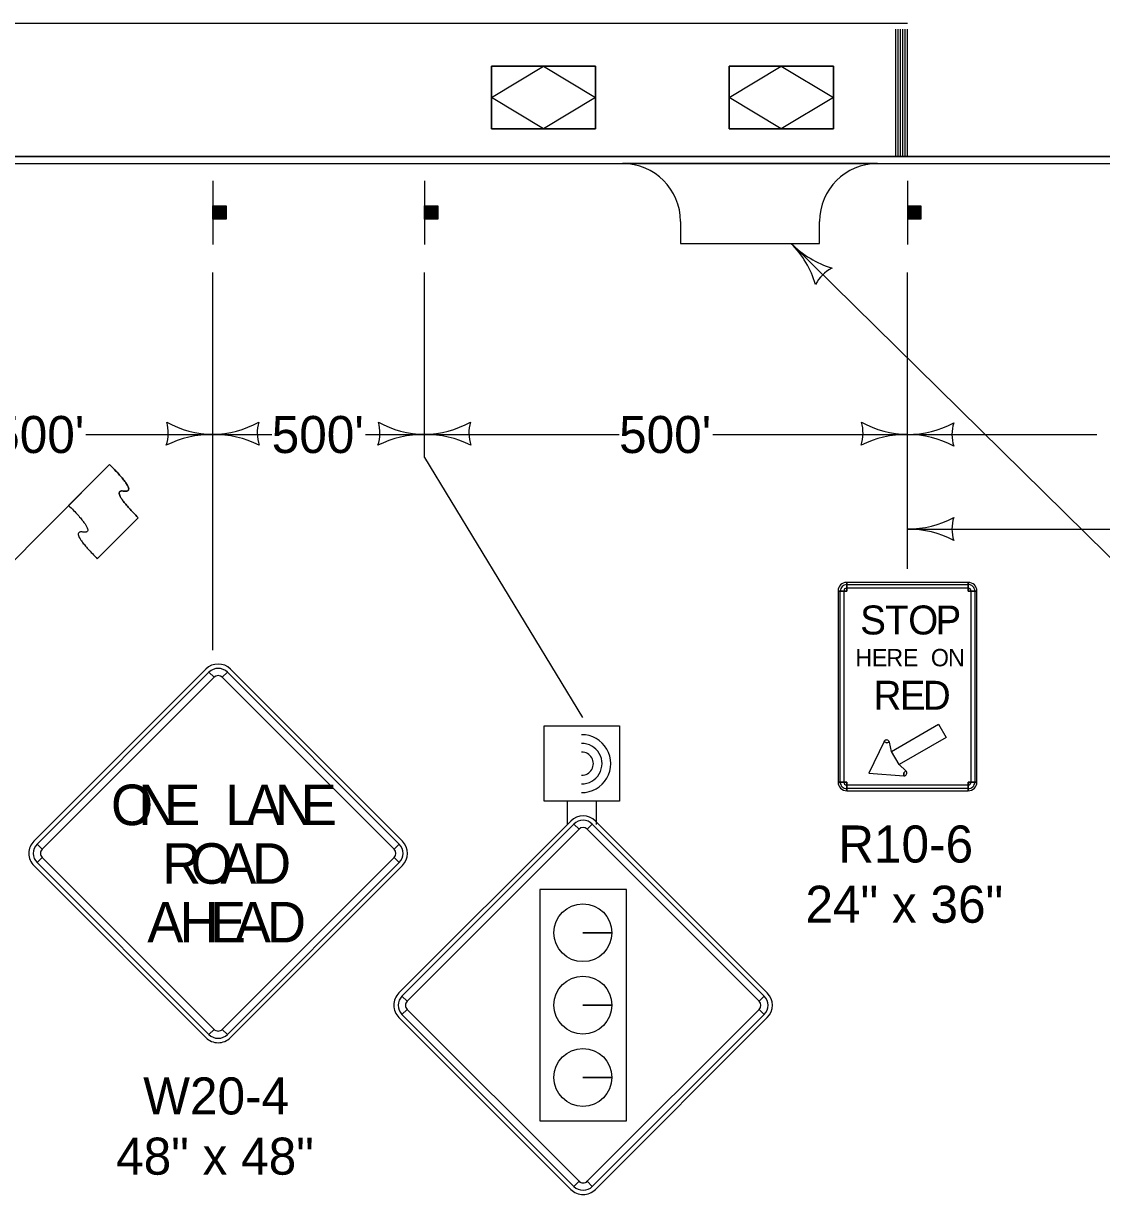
# Model space of a CAD drawing. Extents: x -2134934 to -2122394, y -2140205 to -2137036.
# Drawn here: x -2134616 to -2134151, y -2138113 to -2137608 of the extents above; entities that cross this region are included whole.
import ezdxf

# ---------------------------------------------------------------- set-up
doc = ezdxf.new("R2010")
doc.units = 0
for name, color, linetype in [('Barrier', 7, 'Continuous'), ('BridgeSuperStructureExisting', 7, 'Continuous'), ('DsnShtPlotIdentification', 7, 'Continuous'), ('DsnShtPlotShape', 7, 'Continuous'), ('dsnTextFinalPlan', 7, 'Continuous'), ('TC_Barrier', 7, 'Continuous')]:
    doc.layers.add(name, color=color, linetype=linetype)

msp = doc.modelspace()

# ---------------------------------------------------------------- linework, layer by layer
at = {"layer": 'Barrier'}
for p, q in [((-2134636.31, -2137855.42), (-2134578.99, -2137798.11)), ((-2134578.99, -2137798.11), (-2134596.67, -2137815.79)), ((-2134584.29, -2137838.78), (-2134566.61, -2137821.1)), ((-2134260.69, -2137852.75), (-2134260.69, -2137849)), ((-2134260.69, -2137851.5), (-2134260.69, -2137849.93)), ((-2134208.19, -2137849), (-2134208.19, -2137852.75)), ((-2134208.19, -2137849.93), (-2134208.19, -2137851.5)), ((-2134264.44, -2137852.75), (-2134260.69, -2137852.75)), ((-2134263.5, -2137852.75), (-2134261.94, -2137852.75)), ((-2134208.19, -2137852.75), (-2134204.44, -2137852.75)), ((-2134206.94, -2137852.75), (-2134205.38, -2137852.75)), ((-2134537.4, -2137886.48), (-2134611.65, -2137960.72)), ((-2134536.08, -2137887.8), (-2134533.87, -2137890.01)), ((-2134530.33, -2137890.01), (-2134528.12, -2137887.8)), ((-2134452.55, -2137960.72), (-2134526.8, -2137886.48)), ((-2134244.58, -2137917.73), (-2134243.48, -2137918.31)), ((-2134243.48, -2137918.31), (-2134242.26, -2137918.04)), ((-2134235.13, -2137930.38), (-2134235.98, -2137931.3)), ((-2134260.69, -2137935.24), (-2134264.44, -2137935.24)), ((-2134261.94, -2137935.24), (-2134263.5, -2137935.24)), ((-2134260.69, -2137938.99), (-2134260.69, -2137935.24)), ((-2134235.98, -2137931.3), (-2134236.03, -2137932.55)), ((-2134204.44, -2137935.24), (-2134208.19, -2137935.24)), ((-2134208.19, -2137935.24), (-2134208.19, -2137938.99)), ((-2134205.38, -2137935.24), (-2134206.94, -2137935.24)), ((-2134260.69, -2137938.06), (-2134260.69, -2137936.49)), ((-2134208.19, -2137936.49), (-2134208.19, -2137938.06)), ((-2134379.82, -2137952.07), (-2134454.06, -2138026.31)), ((-2134378.49, -2137953.39), (-2134376.28, -2137955.6)), ((-2134372.75, -2137955.6), (-2134370.54, -2137953.39)), ((-2134294.97, -2138026.31), (-2134369.21, -2137952.07)), ((-2134608.11, -2137964.26), (-2134610.32, -2137962.05)), ((-2134453.88, -2137962.05), (-2134456.08, -2137964.26)), ((-2134611.65, -2137971.33), (-2134537.4, -2138045.58)), ((-2134610.32, -2137970.01), (-2134608.11, -2137967.8)), ((-2134526.8, -2138045.58), (-2134452.55, -2137971.33)), ((-2134456.08, -2137967.8), (-2134453.88, -2137970.01)), ((-2134362.11, -2138000.29), (-2134374.61, -2138000.29)), ((-2134374.61, -2138000.29), (-2134362.11, -2138000.29)), ((-2134450.53, -2138029.85), (-2134452.74, -2138027.64)), ((-2134362.11, -2138031.54), (-2134374.61, -2138031.54)), ((-2134374.61, -2138031.54), (-2134362.11, -2138031.54)), ((-2134296.29, -2138027.64), (-2134298.5, -2138029.85)), ((-2134454.06, -2138036.92), (-2134379.82, -2138111.16)), ((-2134452.74, -2138035.59), (-2134450.53, -2138033.38)), ((-2134369.21, -2138111.16), (-2134294.97, -2138036.92)), ((-2134298.5, -2138033.38), (-2134296.29, -2138035.59)), ((-2134533.87, -2138042.04), (-2134536.08, -2138044.25)), ((-2134528.12, -2138044.25), (-2134530.33, -2138042.04)), ((-2134362.11, -2138062.79), (-2134374.61, -2138062.79)), ((-2134374.61, -2138062.79), (-2134362.11, -2138062.79)), ((-2134376.28, -2138107.63), (-2134378.49, -2138109.84)), ((-2134370.54, -2138109.84), (-2134372.75, -2138107.63))]:
    msp.add_line(p, q, dxfattribs=at)
for points in [[(-2134260.69, -2137938.99), (-2134208.19, -2137938.99), (-2134208.19, -2137935.24), (-2134204.44, -2137935.24), (-2134204.44, -2137852.75), (-2134208.19, -2137852.75), (-2134208.19, -2137849), (-2134260.69, -2137849), (-2134260.69, -2137852.75), (-2134264.44, -2137852.75), (-2134264.44, -2137935.24), (-2134260.69, -2137935.24), (-2134260.69, -2137938.99)], [(-2134208.19, -2137851.5), (-2134260.69, -2137851.5), (-2134260.69, -2137849.93), (-2134208.19, -2137849.93), (-2134208.19, -2137851.5)], [(-2134261.94, -2137852.75), (-2134261.94, -2137935.24), (-2134263.5, -2137935.24), (-2134263.5, -2137852.75), (-2134261.94, -2137852.75)], [(-2134206.94, -2137935.24), (-2134206.94, -2137852.75), (-2134205.38, -2137852.75), (-2134205.38, -2137935.24), (-2134206.94, -2137935.24)], [(-2134536.08, -2137887.8), (-2134610.32, -2137962.05), (-2134608.11, -2137964.26), (-2134533.87, -2137890.01), (-2134536.08, -2137887.8)], [(-2134453.88, -2137962.05), (-2134528.12, -2137887.8), (-2134530.33, -2137890.01), (-2134456.08, -2137964.26), (-2134453.88, -2137962.05)], [(-2134221.07, -2137910.24), (-2134217.79, -2137915.93), (-2134238.1, -2137927.65), (-2134241.38, -2137921.97), (-2134221.07, -2137910.24)], [(-2134251.09, -2137931.37), (-2134236.03, -2137932.55), (-2134235.98, -2137931.3), (-2134235.13, -2137930.38), (-2134238.1, -2137927.65), (-2134241.38, -2137921.97), (-2134242.26, -2137918.04), (-2134243.48, -2137918.31), (-2134244.58, -2137917.73), (-2134251.09, -2137931.37)], [(-2134260.69, -2137936.49), (-2134208.19, -2137936.49), (-2134208.19, -2137938.06), (-2134260.69, -2137938.06), (-2134260.69, -2137936.49)], [(-2134378.49, -2137953.39), (-2134452.74, -2138027.64), (-2134450.53, -2138029.85), (-2134376.28, -2137955.6), (-2134378.49, -2137953.39)], [(-2134296.29, -2138027.64), (-2134370.54, -2137953.39), (-2134372.75, -2137955.6), (-2134298.5, -2138029.85), (-2134296.29, -2138027.64)], [(-2134610.32, -2137970.01), (-2134536.08, -2138044.25), (-2134533.87, -2138042.04), (-2134608.11, -2137967.8), (-2134610.32, -2137970.01)], [(-2134528.12, -2138044.25), (-2134453.88, -2137970.01), (-2134456.08, -2137967.8), (-2134530.33, -2138042.04), (-2134528.12, -2138044.25)], [(-2134355.78, -2137981.67), (-2134393.25, -2137981.67), (-2134393.25, -2138081.56), (-2134355.78, -2138081.56), (-2134355.78, -2137981.67)], [(-2134452.74, -2138035.59), (-2134378.49, -2138109.84), (-2134376.28, -2138107.63), (-2134450.53, -2138033.38), (-2134452.74, -2138035.59)], [(-2134370.54, -2138109.84), (-2134296.29, -2138035.59), (-2134298.5, -2138033.38), (-2134372.75, -2138107.63), (-2134370.54, -2138109.84)]]:
    msp.add_lwpolyline(points, close=True, dxfattribs=at)
for centre in [(-2134374.61, -2138000.29), (-2134374.61, -2138031.54), (-2134374.61, -2138062.79)]:
    msp.add_circle(centre, 12.5, dxfattribs=at)
for centre, radius, start, end in [((-2134260.69, -2137852.75), 3.75, 90.0002, 179.9998), ((-2134260.69, -2137852.75), 2.81, 90.0002, 179.9998), ((-2134208.19, -2137852.75), 3.75, 0, 90.0002), ((-2134208.19, -2137852.75), 2.81, 0, 90.0002), ((-2134260.69, -2137852.75), 1.25, 90.0002, 179.9998), ((-2134208.19, -2137852.75), 1.25, 0, 90.0002), ((-2134532.1, -2137891.78), 7.5, 45, 134.9997), ((-2134532.1, -2137891.78), 5.62, 45, 134.9997), ((-2134532.1, -2137891.78), 2.5, 45, 134.9997), ((-2134243.48, -2137918.31), 1.25, 12.6223, 152.2756), ((-2134235.98, -2137931.3), 1.25, 267.7243, 47.3776), ((-2134260.69, -2137935.24), 3.75, 179.9998, 270.0001), ((-2134260.69, -2137935.24), 2.81, 179.9998, 270.0001), ((-2134260.69, -2137935.24), 1.25, 179.9998, 270.0001), ((-2134208.19, -2137935.24), 3.75, 270.0001, 0.0003), ((-2134208.19, -2137935.24), 2.81, 270.0001, 0.0003), ((-2134208.19, -2137935.24), 1.25, 270.0001, 0.0003), ((-2134374.51, -2137957.37), 7.5, 45, 134.9997), ((-2134374.51, -2137957.37), 5.62, 45, 134.9997), ((-2134374.51, -2137957.37), 2.5, 45, 134.9997), ((-2134606.34, -2137966.03), 7.5, 134.9997, 225), ((-2134457.85, -2137966.03), 7.5, 315.0002, 44.9998), ((-2134606.34, -2137966.03), 5.62, 134.9997, 225), ((-2134606.34, -2137966.03), 2.5, 134.9997, 225), ((-2134457.85, -2137966.03), 2.5, 315.0002, 44.9998), ((-2134457.85, -2137966.03), 5.62, 315.0002, 44.9998), ((-2134448.76, -2138031.62), 7.5, 134.9997, 225), ((-2134300.27, -2138031.62), 7.5, 315.0002, 44.9998), ((-2134448.76, -2138031.62), 5.62, 134.9997, 225), ((-2134448.76, -2138031.62), 2.5, 134.9997, 225), ((-2134300.27, -2138031.62), 2.5, 315.0002, 44.9998), ((-2134300.27, -2138031.62), 5.62, 315.0002, 44.9998), ((-2134532.1, -2138040.27), 2.5, 225, 315.0002), ((-2134532.1, -2138040.27), 7.5, 225, 315.0002), ((-2134532.1, -2138040.27), 5.62, 225, 315.0002), ((-2134374.51, -2138105.86), 2.5, 225, 315.0002), ((-2134374.51, -2138105.86), 7.5, 225, 315.0002), ((-2134374.51, -2138105.86), 5.62, 225, 315.0002)]:
    msp.add_arc(centre, radius, start, end, dxfattribs=at)
for points in [[(-2134566.61, -2137821.1), (-2134578.99, -2137808.72), (-2134566.61, -2137810.49), (-2134578.99, -2137798.11)], [(-2134596.67, -2137815.79), (-2134584.29, -2137828.17), (-2134596.66, -2137826.4), (-2134584.29, -2137838.78)]]:
    msp.add_open_spline(points, degree=2, dxfattribs=at)
at = {"layer": 'BridgeSuperStructureExisting'}
for p, q in [((-2134239.44, -2137665.16), (-2134239.44, -2137610.16)), ((-2134238.44, -2137665.16), (-2134238.44, -2137610.16)), ((-2134237.44, -2137665.16), (-2134237.44, -2137610.16)), ((-2134236.44, -2137665.16), (-2134236.44, -2137610.16)), ((-2134235.44, -2137665.16), (-2134235.44, -2137610.16)), ((-2134234.44, -2137665.16), (-2134234.44, -2137610.16)), ((-2134414.12, -2137653.13), (-2134414.12, -2137626.13)), ((-2134414.12, -2137626.13), (-2134369.12, -2137626.13)), ((-2134414.12, -2137653.13), (-2134414.12, -2137626.13)), ((-2134414.12, -2137626.13), (-2134369.12, -2137626.13)), ((-2134369.12, -2137626.13), (-2134414.12, -2137626.13)), ((-2134414.12, -2137626.13), (-2134414.12, -2137653.13)), ((-2134369.12, -2137653.13), (-2134369.12, -2137626.13)), ((-2134369.12, -2137626.13), (-2134369.12, -2137653.13)), ((-2134369.12, -2137653.13), (-2134369.12, -2137626.13)), ((-2134311.44, -2137653.13), (-2134311.44, -2137626.13)), ((-2134311.44, -2137626.13), (-2134266.44, -2137626.13)), ((-2134311.44, -2137653.13), (-2134311.44, -2137626.13)), ((-2134311.44, -2137626.13), (-2134266.44, -2137626.13)), ((-2134266.44, -2137626.13), (-2134311.44, -2137626.13)), ((-2134311.44, -2137626.13), (-2134311.44, -2137653.13)), ((-2134266.44, -2137653.13), (-2134266.44, -2137626.13)), ((-2134266.44, -2137626.13), (-2134266.44, -2137653.13)), ((-2134266.44, -2137653.13), (-2134266.44, -2137626.13)), ((-2134414.12, -2137653.13), (-2134369.12, -2137653.13)), ((-2134369.12, -2137653.13), (-2134414.12, -2137653.13)), ((-2134414.12, -2137653.13), (-2134369.12, -2137653.13)), ((-2134311.44, -2137653.13), (-2134266.44, -2137653.13)), ((-2134266.44, -2137653.13), (-2134311.44, -2137653.13)), ((-2134311.44, -2137653.13), (-2134266.44, -2137653.13)), ((-2134884.44, -2137665.16), (-2133384.44, -2137665.16)), ((-2134247.44, -2137668.16), (-2134357.44, -2137668.16)), ((-2134534.44, -2137675.66), (-2134534.44, -2137703.16)), ((-2134443.04, -2137675.66), (-2134443.04, -2137703.16)), ((-2134234.44, -2137675.66), (-2134234.44, -2137703.16)), ((-2134534.03, -2137692.11), (-2134534.03, -2137686.52)), ((-2134533.75, -2137686.52), (-2134533.75, -2137692.11)), ((-2134533.48, -2137692.11), (-2134533.48, -2137686.52)), ((-2134533.22, -2137686.52), (-2134533.22, -2137692.11)), ((-2134533, -2137692.11), (-2134533, -2137686.52)), ((-2134532.79, -2137686.52), (-2134532.79, -2137692.11)), ((-2134532.45, -2137692.11), (-2134532.45, -2137686.52)), ((-2134532.19, -2137686.52), (-2134532.19, -2137692.11)), ((-2134531.97, -2137692.11), (-2134531.98, -2137686.52)), ((-2134531.65, -2137686.52), (-2134531.65, -2137692.11)), ((-2134531.27, -2137692.11), (-2134531.27, -2137686.52)), ((-2134530.84, -2137686.52), (-2134530.84, -2137692.11)), ((-2134530.62, -2137692.11), (-2134530.63, -2137686.52)), ((-2134530.2, -2137686.52), (-2134530.18, -2137692.11)), ((-2134529.98, -2137692.11), (-2134529.98, -2137686.52)), ((-2134529.66, -2137686.52), (-2134529.66, -2137692.11)), ((-2134529.43, -2137692.11), (-2134529.43, -2137686.52)), ((-2134529.12, -2137686.52), (-2134529.12, -2137692.11)), ((-2134442.63, -2137692.11), (-2134442.63, -2137686.52)), ((-2134442.35, -2137686.52), (-2134442.35, -2137692.11)), ((-2134442.08, -2137692.11), (-2134442.08, -2137686.52)), ((-2134441.82, -2137686.52), (-2134441.82, -2137692.11)), ((-2134441.6, -2137692.11), (-2134441.6, -2137686.52)), ((-2134441.39, -2137686.52), (-2134441.39, -2137692.11)), ((-2134441.05, -2137692.11), (-2134441.05, -2137686.52)), ((-2134440.79, -2137686.52), (-2134440.79, -2137692.11)), ((-2134440.56, -2137692.11), (-2134440.58, -2137686.52)), ((-2134440.25, -2137686.52), (-2134440.25, -2137692.11)), ((-2134439.87, -2137692.11), (-2134439.87, -2137686.52)), ((-2134439.44, -2137686.52), (-2134439.44, -2137692.11)), ((-2134439.21, -2137692.11), (-2134439.23, -2137686.52)), ((-2134438.8, -2137686.52), (-2134438.78, -2137692.11)), ((-2134438.58, -2137692.11), (-2134438.58, -2137686.52)), ((-2134438.26, -2137686.52), (-2134438.26, -2137692.11)), ((-2134438.03, -2137692.11), (-2134438.03, -2137686.52)), ((-2134437.71, -2137686.52), (-2134437.71, -2137692.11)), ((-2134234.03, -2137692.11), (-2134234.03, -2137686.52)), ((-2134233.75, -2137686.52), (-2134233.75, -2137692.11)), ((-2134233.49, -2137692.11), (-2134233.49, -2137686.52)), ((-2134233.22, -2137686.52), (-2134233.22, -2137692.11)), ((-2134233, -2137692.11), (-2134233, -2137686.52)), ((-2134232.79, -2137686.52), (-2134232.79, -2137692.11)), ((-2134232.45, -2137692.11), (-2134232.45, -2137686.52)), ((-2134232.19, -2137686.52), (-2134232.19, -2137692.11)), ((-2134231.97, -2137692.11), (-2134231.99, -2137686.52)), ((-2134231.65, -2137686.52), (-2134231.65, -2137692.11)), ((-2134231.27, -2137692.11), (-2134231.27, -2137686.52)), ((-2134230.84, -2137686.52), (-2134230.84, -2137692.11)), ((-2134230.62, -2137692.11), (-2134230.64, -2137686.52)), ((-2134230.2, -2137686.52), (-2134230.19, -2137692.11)), ((-2134229.98, -2137692.11), (-2134229.98, -2137686.52)), ((-2134229.66, -2137686.52), (-2134229.66, -2137692.11)), ((-2134229.44, -2137692.11), (-2134229.44, -2137686.52)), ((-2134229.12, -2137686.52), (-2134229.12, -2137692.11)), ((-2134096.53, -2137887.94), (-2134284.66, -2137702.65)), ((-2134534.44, -2137878.33), (-2134534.44, -2137715.16)), ((-2134443.04, -2137795.16), (-2134443.04, -2137715.16)), ((-2134234.44, -2137843.11), (-2134234.44, -2137715.16)), ((-2134589.19, -2137785.16), (-2134534.44, -2137785.16)), ((-2134534.44, -2137785.16), (-2134508.99, -2137785.16)), ((-2134468.49, -2137785.16), (-2134443.04, -2137785.16)), ((-2134443.04, -2137785.16), (-2134358.99, -2137785.16)), ((-2134318.49, -2137785.16), (-2134234.44, -2137785.16)), ((-2134234.44, -2137785.16), (-2134152.68, -2137785.16)), ((-2134443.04, -2137795.16), (-2134374.84, -2137907.34)), ((-2134234.44, -2137825.98), (-2133930.88, -2137825.98)), ((-2134381.36, -2137943.52), (-2134381.36, -2137953.52)), ((-2134368.86, -2137943.52), (-2134368.86, -2137953.52))]:
    msp.add_line(p, q, dxfattribs=at)
for points in [[(-2134534.35, -2137692.11), (-2134534.35, -2137686.48), (-2134528.72, -2137686.48), (-2134528.72, -2137692.11)], [(-2134442.95, -2137692.11), (-2134442.95, -2137686.48), (-2134437.32, -2137686.48), (-2134437.32, -2137692.11)], [(-2134234.35, -2137692.11), (-2134234.35, -2137686.48), (-2134228.72, -2137686.48), (-2134228.72, -2137692.11)], [(-2134391.36, -2137943.52), (-2134391.36, -2137911.02), (-2134358.86, -2137911.02), (-2134358.86, -2137943.52)]]:
    msp.add_lwpolyline(points, close=True, dxfattribs=at)
msp.add_lwpolyline([(-2134332.44, -2137693.16), (-2134332.44, -2137702.65), (-2134272.44, -2137702.65), (-2134272.44, -2137693.16)], dxfattribs=at)
for centre, radius, start, end in [((-2134357.44, -2137693.16), 25, 0, 90), ((-2134247.44, -2137693.16), 25, 90, 180), ((-2134570.06, -2137784.54), 16.42, 341.2666, 16.7334), ((-2134533.69, -2137742.67), 42.5, 240.9275, 268.9824), ((-2134535.2, -2137742.67), 42.5, 271.0176, 299.0725), ((-2134498.82, -2137784.54), 16.42, 163.2666, 198.7334), ((-2134478.66, -2137784.54), 16.42, 341.2666, 16.7334), ((-2134442.29, -2137742.67), 42.5, 240.9275, 268.9824), ((-2134443.79, -2137742.67), 42.5, 271.0176, 299.0725), ((-2134407.42, -2137784.54), 16.42, 163.2666, 198.7334), ((-2134270.06, -2137784.54), 16.42, 341.2666, 16.7334), ((-2134233.69, -2137742.67), 42.5, 240.9275, 268.9824), ((-2134234.44, -2137742.66), 42.5, 270, 298.0725), ((-2134198.81, -2137785.16), 16.42, 162.2666, 197.7334), ((-2134535.17, -2137827.65), 42.5, 89.0176, 117.0725), ((-2134533.71, -2137827.65), 42.5, 62.9275, 90.9824), ((-2134443.77, -2137827.65), 42.5, 89.0176, 117.0725), ((-2134442.31, -2137827.65), 42.5, 62.9275, 90.9824), ((-2134235.17, -2137827.65), 42.5, 89.0176, 117.0725), ((-2134234.44, -2137827.66), 42.5, 61.9275, 90), ((-2134375.1, -2137927.28), 12.5, 269.4041, 90.5445), ((-2134375.1, -2137927.28), 12.5, 269.4041, 90.5445), ((-2134375.1, -2137927.28), 8.75, 269.4041, 90.5445), ((-2134375.1, -2137927.28), 5, 269.4041, 90.5445)]:
    msp.add_arc(centre, radius, start, end, dxfattribs=at)
at = {"layer": 'DsnShtPlotIdentification'}
for p, q in [((-2134234.44, -2137607.66), (-2134886.94, -2137607.66)), ((-2134884.44, -2137665.16), (-2133384.44, -2137665.16)), ((-2134884.44, -2137665.16), (-2133384.44, -2137665.16)), ((-2134239.44, -2137665.16), (-2134884.44, -2137665.16)), ((-2134884.44, -2137668.16), (-2133384.44, -2137668.16)), ((-2134884.44, -2137668.16), (-2133384.44, -2137668.16)), ((-2134238.44, -2137665.16), (-2134239.44, -2137665.16)), ((-2134237.44, -2137665.16), (-2134238.44, -2137665.16)), ((-2134236.44, -2137665.16), (-2134237.44, -2137665.16)), ((-2133384.44, -2137665.16), (-2134234.44, -2137665.16))]:
    msp.add_line(p, q, dxfattribs=at)
msp.add_lwpolyline([(-2134234.44, -2137665.16), (-2134235.44, -2137665.16), (-2134236.44, -2137665.16)], dxfattribs=at)
at = {"layer": 'DsnShtPlotShape'}
for centre, radius, start, end in [((-2134314.86, -2137732.56), 42.5, 16.6579, 44.7304), ((-2134254.47, -2137672.74), 42.5, 224.7304, 252.8028), ((-2134259.59, -2137727.96), 16.42, 116.997, 152.4637), ((-2134234.44, -2137783.48), 42.5, 270, 298.0725), ((-2134198.81, -2137825.98), 16.42, 162.2666, 197.7334), ((-2134234.44, -2137868.48), 42.5, 61.9275, 90)]:
    msp.add_arc(centre, radius, start, end, dxfattribs=at)
at = {"layer": 'dsnTextFinalPlan'}
for points in [[(-2134414.12, -2137639.63), (-2134391.62, -2137626.13), (-2134369.12, -2137639.63), (-2134391.62, -2137653.13)], [(-2134311.44, -2137639.63), (-2134288.94, -2137626.13), (-2134266.44, -2137639.63), (-2134288.94, -2137653.13)]]:
    msp.add_lwpolyline(points, close=True, dxfattribs=at)
at = {"layer": 'TC_Barrier'}
msp.add_line((-2134566.61, -2137821.1), (-2134584.29, -2137838.78), dxfattribs=at)
for points in [[(-2134578.99, -2137798.11), (-2134566.61, -2137810.49), (-2134578.99, -2137808.72), (-2134566.61, -2137821.1)], [(-2134596.67, -2137815.79), (-2134584.29, -2137828.17), (-2134596.66, -2137826.4), (-2134584.29, -2137838.78)]]:
    msp.add_open_spline(points, degree=2, dxfattribs=at)

# ---------------------------------------------------------------- texts
at = {"layer": 'Barrier'}
for s, height, p in [('S', 12.5, (-2134254.89, -2137871.5)), ('T', 12.5, (-2134244.13, -2137871.5)), ('O', 12.5, (-2134234.14, -2137871.5)), ('P', 12.5, (-2134222.39, -2137871.5)), ('H', 7.5, (-2134256.97, -2137885.25)), ('E', 7.5, (-2134249.82, -2137885.25)), ('R', 7.5, (-2134243.56, -2137885.25)), ('E', 7.5, (-2134236.41, -2137885.25)), ('O', 7.5, (-2134224.34, -2137885.25)), ('N', 7.5, (-2134216.96, -2137885.25)), ('R', 12.5, (-2134249.13, -2137904)), ('E', 12.5, (-2134237.8, -2137904)), ('D', 12.5, (-2134227.84, -2137904)), ('O', 17.5, (-2134578.38, -2137953.84)), ('N', 17.5, (-2134566.61, -2137953.84)), ('E', 17.5, (-2134555.38, -2137953.84)), ('L', 17.5, (-2134529.13, -2137953.84)), ('A', 17.5, (-2134519.93, -2137953.84)), ('N', 17.5, (-2134507.67, -2137953.84)), ('E', 17.5, (-2134496.44, -2137953.84)), ('R10-6', 16, (-2134264.37, -2137969.99)), ('O', 17.5, (-2134543.99, -2137979.15)), ('R', 17.5, (-2134556.28, -2137979.15)), ('A', 17.5, (-2134531.15, -2137979.15)), ('D', 17.5, (-2134517.49, -2137979.15)), ('24" x 36"', 16, (-2134278.51, -2137995.99)), ('A', 17.5, (-2134562.71, -2138004.47)), ('H', 17.5, (-2134548.85, -2138004.47)), ('E', 17.5, (-2134535.63, -2138004.47)), ('A', 17.5, (-2134524.92, -2138004.47)), ('D', 17.5, (-2134511.05, -2138004.47)), ('W20-4', 16, (-2134564.47, -2138078.77)), ('48" x 48"', 16, (-2134576.17, -2138104.77))]:
    msp.add_text(s, height=height, dxfattribs=at).set_placement(p)
at = {"layer": 'BridgeSuperStructureExisting'}
for p in [(-2134629.69, -2137793.16), (-2134508.99, -2137793.16), (-2134358.99, -2137793.16)]:
    msp.add_text("500'", height=16, dxfattribs=at).set_placement(p)

doc.saveas('drawing.dxf')
